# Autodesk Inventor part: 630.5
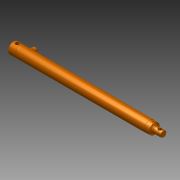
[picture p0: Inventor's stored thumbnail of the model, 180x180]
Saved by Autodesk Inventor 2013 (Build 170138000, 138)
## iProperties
Created: 2015-07
Part Number: 630.5
Material: Générique
Document SubType Name: Modeling
Designer: OL
Density: 1 g/cm^3
Author: OL
Norme de conversion: STEP AP203
Nom du fichier: 630.5.STEP
Préprocesseur: SolidWorks 2013
Postprocesseur: Build: 138, Release: 2013 RTM - Date: Thu 03/01/2012
Unités envoyées: millimètre
Incertitude: 1e-05
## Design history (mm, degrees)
node "630.51"
feature "Composite1"
body "Srf1"
